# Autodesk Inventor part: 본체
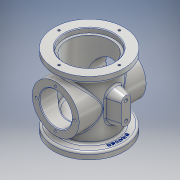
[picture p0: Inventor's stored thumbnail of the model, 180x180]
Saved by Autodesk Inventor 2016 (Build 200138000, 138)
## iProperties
Created: 2018-02
Part Number: 본체
Material: 알루미늄 6061
Document SubType Name: Modeling
Designer: 605-15
Density: 2.7 g/cm^3
Appearance: 알루미늄 - 평지
Mass: 831.863 g
Surface Area: 810.089 cm^2
Volume: 308.097 cm^3
Author: 605-15
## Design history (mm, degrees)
sketch "스케치2"
  geometry: L1 (-50, 0)-(50, 0); L2 (50, 0)-(50, 35); L3 (50, 35)-(-50, 35); L4 (-50, 35)-(-50, 0); 2 further points
  constraints: 8 end point, 2 parallel, 1 coincident, 1 horizontal, 1 midpoint, 1 perpendicular
  dimensions: "d4" = 100 distance of L3.end L2.end; "d5" = 70 diameter of L3 L1
revolve "회전2" sketch "스케치2" stored, may be unused: angle "d6" = 90 deg
sketch "스케치3"
  geometry: L1 (-38, 44)-(38, 44); L2 (38, 44)-(38, -44); L3 (38, -44)-(-38, -44); L4 (-38, -44)-(-38, 44); L5 (-52.5, -44)-(52.5, -44); L6 (52.5, -44)-(52.5, -54); L7 (52.5, -54)-(-52.5, -54); L8 (-52.5, -54)-(-52.5, -44); L9 (-52.5, 44)-(52.5, 44); L10 (52.5, 44)-(52.5, 54); L11 (52.5, 54)-(-52.5, 54); L12 (-52.5, 54)-(-52.5, 44); L13 (0, 54)-(0, -54); L14 (-34, -54)-(34, -54); L15 (-33, 54)-(33, 54); L16 (5, -38)-(-5, -38); L17 (34, -54)-(52.5, -54); L18 (52.5, -54)-(52.5, -44); L19 (52.5, -44)-(38, -44); L20 (38, -44)-(38, 44); L21 (38, 44)-(52.5, 44); L22 (52.5, 44)-(52.5, 54); L23 (52.5, 54)-(33, 54); 6 further points
  constraints: 46 end point, 8 midpoint, 6 parallel, 5 collinear, 5 horizontal, 5 perpendicular, 3 point on line, 1 horizontal alignment, 1 vertical alignment
  dimensions: "d7" = 76 distance of L2.end L3.end; "d8" = 105 distance of L6.end L7.end; "d9" = 10 distance of L5.end L6.end; "d10" = 105 distance of L11.end L10.end; "d11" = 10 distance of L10.end L9.end; "d12" = 54 distance from line of point (38, 0) L7; "d17" = 10 distance of L16.start L16.end
revolve "회전3" sketch "스케치3" stored, may be unused: angle "d18" = 90 deg
hole "구멍1" diameter "d21" = 66; stored, may be unused: countersink angle "d25" = 90 deg, drill point angle "d27" = 0 deg; dims "d19" = 10, "d20" = 10, "d22" = 6, "d23" = 4, "d24" = 2, "d26" = 79
hole "구멍2" diameter "d30" = 68; stored, may be unused: countersink angle "d34" = 90 deg, drill point angle "d36" = 0 deg; dims "d28" = 10, "d29" = 10, "d31" = 6, "d32" = 4, "d33" = 2, "d35" = 16
hole "구멍3" diameter "d39" = 10; stored, may be unused: countersink angle "d43" = 90 deg, drill point angle "d45" = 0 deg; dims "d37" = 10, "d38" = 10, "d40" = 6, "d41" = 4, "d42" = 2, "d44" = 16
hole "구멍4" diameter "d48" = 74; stored, may be unused: countersink angle "d52" = 90 deg, drill point angle "d54" = 0 deg; dims "d46" = 10, "d47" = 10, "d49" = 6, "d50" = 4, "d51" = 2, "d53" = 7
hole "구멍5" diameter "d57" = 48; stored, may be unused: countersink angle "d61" = 90 deg, drill point angle "d63" = 0 deg; dims "d55" = 10, "d56" = 10, "d58" = 6, "d59" = 4, "d60" = 2, "d62" = 7
sketch "스케치4" dims "d64" = 58
  geometry: 3 further points
  constraints: 2 vertical alignment, 1 coincident, 2 other
hole "구멍6" sketch "스케치4" at (0, -29) diameter "d65" = 3.459; stored, may be unused: countersink angle "d69" = 90 deg, drill point angle "d71" = 118 deg; dims "d66" = 4, "d67" = 4, "d68" = 2, "d70" = 6
sketch "스케치5" dims "d75" = 90
  geometry: 3 further points
  constraints: 2 vertical alignment, 1 coincident, 2 other
hole "구멍7" sketch "스케치5" at (0, 45) diameter "d76" = 3.242; stored, may be unused: countersink angle "d80" = 90 deg, drill point angle "d82" = 118 deg; dims "d77" = 4, "d78" = 4, "d79" = 2, "d81" = 6
node "작업 평면2"
sketch "스케치6"
  geometry: L1 (0, 20)-(0, -20); L2 (7, 13)-(7, -13); L3 (-7, 13)-(-7, -13); A1 r 7 centre (0, -13) between (0, -20) and (7, -13); A2 r 7 centre (0, 13) between (0, 20) and (7, 13); 2 further points
  constraints: 6 end point, 6 point on circle, 4 tangent, 2 centre point, 2 point on line, 1 coincident, 1 midpoint, 1 vertical
  dimensions: "d88" = 7 radius of A1; "d89" = 7 radius of A2; "d90" = 40 distance of L1.start L1.end
extrude "돌출1" join sketch "스케치6" stored distance "d91" = 10; taper "d92" = 15 deg
sketch "스케치7"
  geometry: L1 (13, 7)-(-13, 7) reference; L2 (-13, -7)-(13, -7) reference; A1 r 7 centre (13, 0) between (13, -7) and (13, 7) reference; A2 r 7 centre (-13, 0) between (-13, 7) and (-13, -7) reference; 3 further points
  constraints: 2 coincident
hole "구멍8" sketch "스케치7" at (-13, 0), (13, 0) diameter "d93" = 4.459; stored, may be unused: countersink angle "d97" = 90 deg, drill point angle "d99" = 118 deg; dims "d94" = 6, "d95" = 4, "d96" = 2, "d98" = 8
fillet "모깎기1" dims "d100" = 3
chamfer "모따기1" distance "d101" = 1; stored, may be unused: second distance "d102" = 2, angle "d103" = 45 deg
node "작업 평면3"
sketch "스케치8"
  geometry: C1 r 43 at (0, 0); 1 further point
  constraints: 1 centre point, 1 coincident, 1 other
  dimensions: "d105" = 86 diameter of C1
feature "엠보싱2" sketch "스케치8" dims "d4" = 100, "d5" = 70, "d7" = 76, "d8" = 105, "d9" = 10, "d10" = 105, "d11" = 10, "d12" = 54, "d109" = 0.5, "d110" = 0
node "솔리드2"
pattern_circular "원형 패턴1" dims angle "d73" = 360 deg
mirror "대칭1"
pattern_circular "원형 패턴2" dims angle "d84" = 360 deg
node "투영된 루프1"
other parameters: "d86" = 55, "d104" = 5
